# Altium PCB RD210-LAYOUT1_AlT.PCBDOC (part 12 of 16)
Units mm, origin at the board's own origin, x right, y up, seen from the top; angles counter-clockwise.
Board outline 330 x 300 mm, 6 copper layers (TOP, Mid-Layer 1, Mid-Layer 2, Mid-Layer 3, Mid-Layer 4, BOTTOM), stack 1.422 mm thick; 981 components, 463 nets, 2326 pads, 12534 vias.
Unrouted connection lines stored in the file: 6.
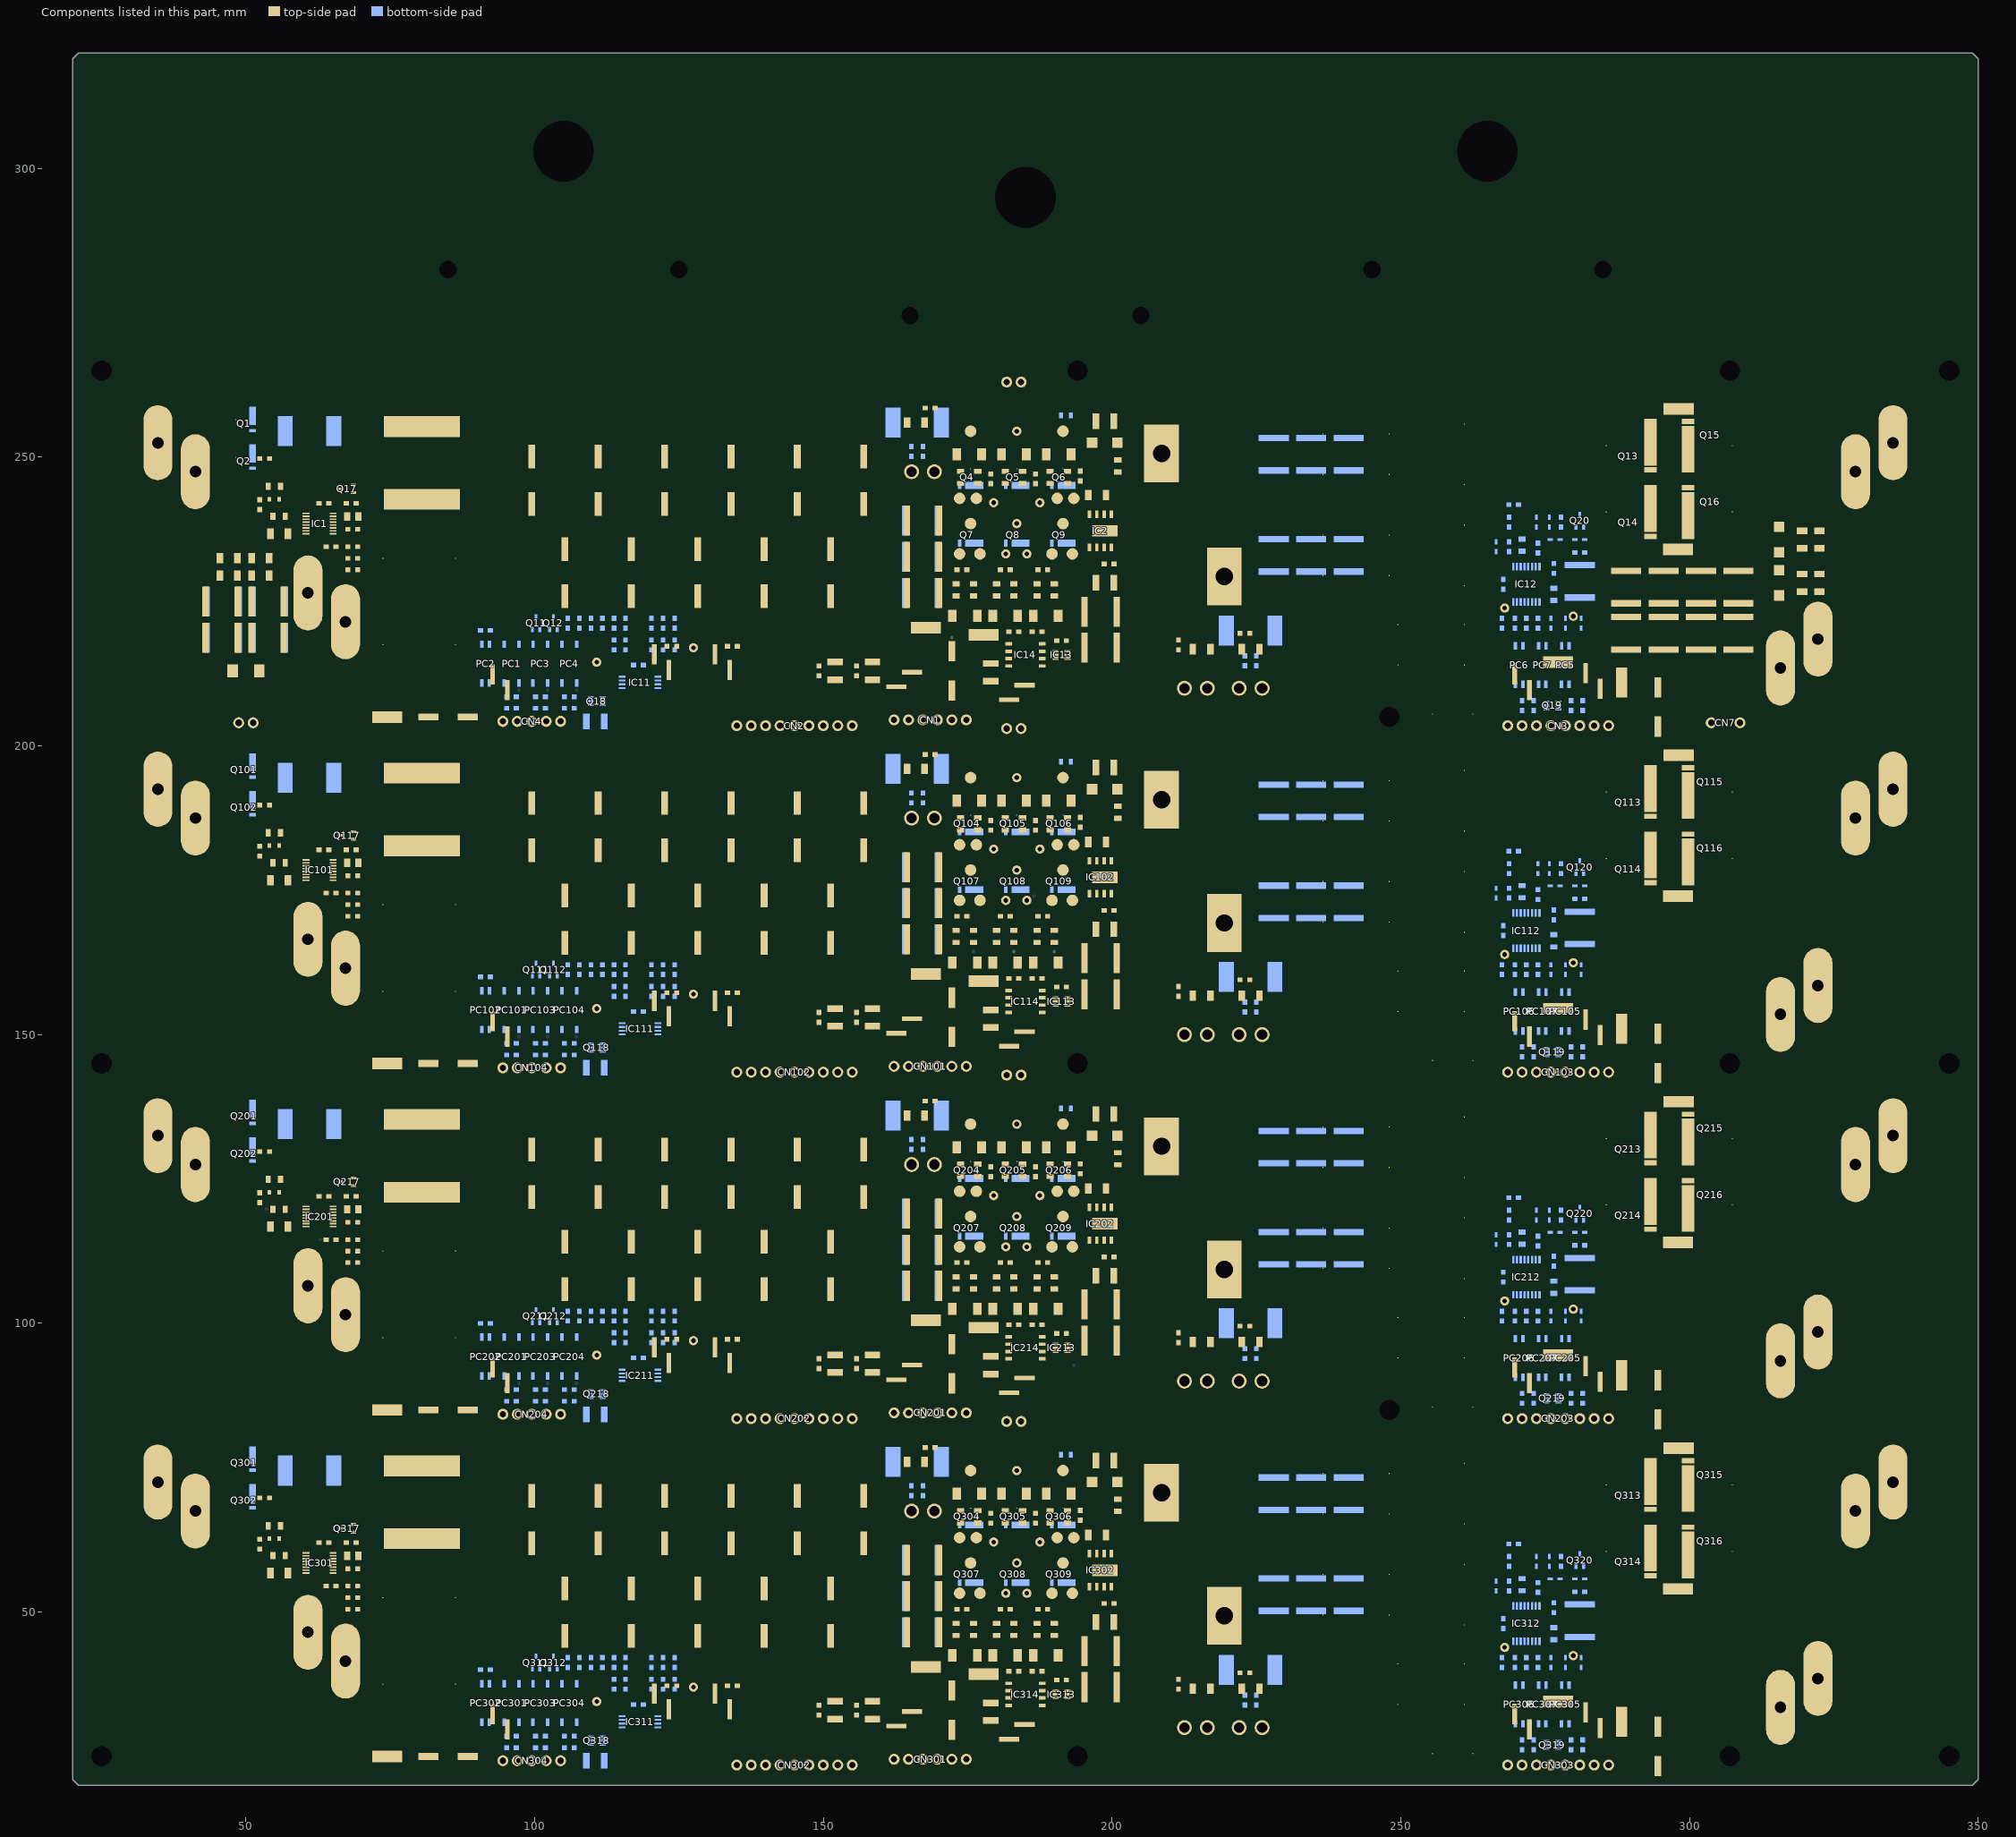
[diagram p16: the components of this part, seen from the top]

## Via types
v1: diameter 0.8, hole 0.3, TOP to BOTTOM, 12534 vias

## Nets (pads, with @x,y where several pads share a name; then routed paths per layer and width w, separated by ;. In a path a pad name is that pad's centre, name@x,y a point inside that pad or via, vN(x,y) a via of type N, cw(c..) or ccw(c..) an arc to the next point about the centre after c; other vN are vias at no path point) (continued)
pads on no net: CN2.3 CN2.4 CN2.5 CN7.2 CN102.3 CN102.4 CN102.5 CN202.3 CN202.4 CN202.5 CN302.3 CN302.4 CN302.5 IC1.3 IC1.4 IC1.7 IC1.14 IC12.11 IC12.15 IC101.3 IC101.4 IC101.7 IC101.14 IC112.11 IC112.15 IC201.3 IC201.4 IC201.7 IC201.14 IC212.11 IC212.15 IC301.3 IC301.4 IC301.7 IC301.14 IC312.11 IC312.15

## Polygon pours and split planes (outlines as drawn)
VP_L on TOP "TOP3" (solid, pour order 288): 94 vertices, not listed, extent 285,201 339,259.5
GND_P-1 on TOP "TOP4" (solid, pour order 289): 1025 vertices, not listed, extent 50.5,201 79.5,243.25
N00100041 on TOP "TOP5" (solid, pour order 290): 107 vertices, not listed, extent 61.5,29.875 89.5,79.5
VP_L on TOP "TOP10" (solid, pour order 295): 94 vertices, not listed, extent 285,21 339,79.5
VP_H on TOP "TOP11" (solid, pour order 296): 77 vertices, not listed, extent 31,141 54,199.5
VP_H on TOP "TOP12" (solid, pour order 297): 77 vertices, not listed, extent 31,81 54,139.5
VP_H on TOP "TOP13" (solid, pour order 298): 77 vertices, not listed, extent 31,21 54,79.5
GND_P-2 on TOP "TOP14" (solid, pour order 299): 985 vertices, not listed, extent 50.5,141 79.5,183.25
GND_P-3 on TOP "TOP15" (solid, pour order 300): 984 vertices, not listed, extent 50.5,81 79.5,123.25
GND_P-4 on TOP "TOP16" (solid, pour order 301): 986 vertices, not listed, extent 50.5,21 79.5,63.25
VP_L on TOP "TOP17" (solid, pour order 302): 94 vertices, not listed, extent 285,141 339,199.5
VP_L on TOP "TOP18" (solid, pour order 303): 94 vertices, not listed, extent 285,81 339,139.5
no net on TOP "TOP19" (solid, pour order 304): 41 vertices, not listed, extent 21,11 349,19
no net on TOP "TOP20" (solid, pour order 305): 41 vertices, not listed, extent 21,321 349,329
N00100195 on TOP "TOP21" (solid, pour order 306): 88 vertices, not listed, extent 199,244 213,259.5
I_SEN_N_3-1 on TOP "TOP22" (solid, pour order 307): 88 vertices, not listed, extent 214,218.5 223.5,236.125
I_SEN_N_3-2 on TOP "TOP23" (solid, pour order 308): 88 vertices, not listed, extent 214,158.5 223.5,176.125
I_SEN_N_3-3 on TOP "TOP24" (solid, pour order 309): 88 vertices, not listed, extent 214,98.5 223.5,116.125
I_SEN_N_3-4 on TOP "TOP25" (solid, pour order 310): 88 vertices, not listed, extent 214,38.5 223.5,56.125
GND-1 on TOP "TOP27" (solid, pour order 312): 44 vertices, not listed, extent 182.95,213.25 184.75,219.1
N00300246 on TOP "TOP28" (solid, pour order 313): 41 vertices, not listed, extent 171.5,253 194.75,259.5
N00300259 on TOP "TOP29" (solid, pour order 314): 280 vertices, not listed, extent 292.15,232.875 300.85,259.5
VDDIO-1 on TOP "TOP30" (solid, pour order 315): 118 vertices, not listed, extent 148.25,203.5 163.25,212.75
GND-1 on TOP "TOP31" (solid, pour order 316): 93 vertices, not listed, extent 100.5,204.879 103.5,206
GND-1 on TOP "TOP32" (solid, pour order 317): 76 vertices, not listed, extent 166,205.129 168.5,206
GND-1 on TOP "TOP33" (solid, pour order 318): 624 vertices, not listed, extent 98,201 169,216.125
VP_5R0-1 on TOP "TOP34" (solid, pour order 319): 156 vertices, not listed, extent 154.5,203.5 165.75,212.75
N00200025 on TOP "TOP35" (solid, pour order 320): 41 vertices, not listed, extent 171.5,193 194.75,199.5
N00200017 on TOP "TOP36" (solid, pour order 321): 88 vertices, not listed, extent 199,184 213,199.5
GND-2 on TOP "TOP37" (solid, pour order 322): 44 vertices, not listed, extent 182.95,153.25 184.75,159.1
N00300090 on TOP "TOP38" (solid, pour order 323): 41 vertices, not listed, extent 171.75,133 194.75,139.5
GND-2 on TOP "TOP39" (solid, pour order 324): 93 vertices, not listed, extent 100.5,144.879 103.5,146
GND-2 on TOP "TOP40" (solid, pour order 325): 76 vertices, not listed, extent 166,145.129 168.5,146
GND-2 on TOP "TOP41" (solid, pour order 326): 628 vertices, not listed, extent 98,141 169,156.125
VDDIO-2 on TOP "TOP42" (solid, pour order 327): 118 vertices, not listed, extent 148.25,143.5 163.25,152.75
VP_5R0-2 on TOP "TOP43" (solid, pour order 328): 156 vertices, not listed, extent 154.5,143.5 165.75,152.75
GND_P-1 on TOP "TOP44" (solid, pour order 329): 127 vertices, not listed, extent 285,201 327,227.75
N00300062 on TOP "TOP45" (solid, pour order 330): 88 vertices, not listed, extent 199,124 213,139.5
GND_P-2 on TOP "TOP46" (solid, pour order 331): 231 vertices, not listed, extent 285,141 327,167.75
VP_12R0_SYS_I0_0 on TOP "TOP47" (solid, pour order 332): 122 vertices, not listed, extent 182.053,209.25 201.75,232.604
GND_P-3 on TOP "TOP48" (solid, pour order 333): 65 vertices, not listed, extent 188.75,95.475 189.45,96.025
GND_P-3 on TOP "TOP49" (solid, pour order 334): 194 vertices, not listed, extent 188.75,96.76 191.725,99.375
GND_P-3 on TOP "TOP50" (solid, pour order 335): 184 vertices, not listed, extent 188.75,93.25 199.355,113.5
GND_P-3 on TOP "TOP51" (solid, pour order 336): 308 vertices, not listed, extent 185.25,93.25 193.125,106.25
GND_P-3 on TOP "TOP52" (solid, pour order 337): 445 vertices, not listed, extent 167.5,102 201,123.125
VP_12R0_SYS_I2_0 on TOP "TOP53" (solid, pour order 338): 122 vertices, not listed, extent 182.053,89.25 201.75,112.604
GND-3 on TOP "TOP54" (solid, pour order 339): 93 vertices, not listed, extent 100.5,84.879 103.5,86
GND-3 on TOP "TOP55" (solid, pour order 340): 76 vertices, not listed, extent 166,85.129 168.5,86
GND-3 on TOP "TOP56" (solid, pour order 341): 628 vertices, not listed, extent 98,81 169,96.125
VDDIO-3 on TOP "TOP57" (solid, pour order 342): 118 vertices, not listed, extent 148.25,83.5 163.25,92.75
VP_5R0-3 on TOP "TOP58" (solid, pour order 343): 156 vertices, not listed, extent 154.5,83.5 165.75,92.75
GND_P-3 on TOP "TOP59" (solid, pour order 344): 87 vertices, not listed, extent 285,81 327,107.75
GND-4 on TOP "TOP60" (solid, pour order 345): 93 vertices, not listed, extent 100.5,24.879 103.5,26
GND-4 on TOP "TOP61" (solid, pour order 346): 76 vertices, not listed, extent 166,25.129 168.5,26
GND-4 on TOP "TOP62" (solid, pour order 347): 628 vertices, not listed, extent 98,21 169,36.125
VP_5R0-4 on TOP "TOP63" (solid, pour order 348): 157 vertices, not listed, extent 154.5,23.5 165.75,32.75
VDDIO-4 on TOP "TOP64" (solid, pour order 349): 118 vertices, not listed, extent 148.25,23.5 163.25,32.75
VP_12R0_SYS_I3_0 on TOP "TOP65" (solid, pour order 350): 139 vertices, not listed, extent 182.053,29.25 201.75,52.604
GND_P-4 on TOP "TOP66" (solid, pour order 351): 65 vertices, not listed, extent 188.75,35.475 189.45,36.025
GND_P-4 on TOP "TOP67" (solid, pour order 352): 194 vertices, not listed, extent 188.75,36.76 191.725,39.375
GND_P-4 on TOP "TOP68" (solid, pour order 353): 183 vertices, not listed, extent 188.75,33.25 199.355,53.5
GND_P-4 on TOP "TOP69" (solid, pour order 354): 308 vertices, not listed, extent 185.25,33.25 193.125,46.25
GND_P-4 on TOP "TOP70" (solid, pour order 355): 447 vertices, not listed, extent 167.5,42 201,63.125
N00400068 on TOP "TOP71" (solid, pour order 356): 41 vertices, not listed, extent 171.5,73 194.75,79.5
N00400069 on TOP "TOP72" (solid, pour order 357): 88 vertices, not listed, extent 199,64 213,79.5
GND_P-4 on TOP "TOP73" (solid, pour order 358): 230 vertices, not listed, extent 285,21 327,47.75
N00100060 on TOP "TOP74" (solid, pour order 359): 280 vertices, not listed, extent 292.15,52.875 300.85,79.5
N00300065 on TOP "TOP75" (solid, pour order 360): 280 vertices, not listed, extent 292.15,112.875 300.85,139.5
N00400061 on TOP "TOP76" (solid, pour order 361): 280 vertices, not listed, extent 292.15,172.875 300.85,199.5
GND-4 on TOP "TOP77" (solid, pour order 362): 44 vertices, not listed, extent 182.95,33.25 184.75,39.1
GND-3 on TOP "TOP78" (solid, pour order 363): 44 vertices, not listed, extent 182.95,93.25 184.75,99.1
VP_12R0_SYS_I1_0 on TOP "TOP79" (solid, pour order 364): 105 vertices, not listed, extent 182.053,149.25 201.75,172.604
N00400042 on TOP "TOP82" (solid, pour order 367): 107 vertices, not listed, extent 61.5,149.875 89.5,199.5
N00300240 on TOP "TOP84" (solid, pour order 369): 107 vertices, not listed, extent 61.5,209.875 89.5,259.5
N00300046 on TOP "TOP86" (solid, pour order 371): 107 vertices, not listed, extent 61.5,89.875 89.5,139.5
N00300241 on TOP "TOP88" (solid, pour order 373): 164 vertices, not listed, extent 50.5,247.5 60.5,259.5
N00400043 on TOP "TOP89" (solid, pour order 374): 164 vertices, not listed, extent 50.5,187.5 60.5,199.5
N00300047 on TOP "TOP90" (solid, pour order 375): 164 vertices, not listed, extent 50.5,127.5 60.5,139.5
N00100042 on TOP "TOP91" (solid, pour order 376): 164 vertices, not listed, extent 50.5,67.5 60.5,79.5
GND_P-1 on TOP "TOP93" (solid, pour order 378): 41 vertices, not listed, extent 214,237.125 223.5,244
GND_P-1 on TOP "TOP94" (solid, pour order 379): 65 vertices, not listed, extent 188.75,215.475 189.45,216.025
GND_P-1 on TOP "TOP95" (solid, pour order 380): 194 vertices, not listed, extent 188.75,216.76 191.725,219.375
GND_P-1 on TOP "TOP96" (solid, pour order 381): 184 vertices, not listed, extent 188.75,213.25 199.355,233.5
GND_P-1 on TOP "TOP97" (solid, pour order 382): 308 vertices, not listed, extent 185.25,213.25 193.125,226.25
GND_P-1 on TOP "TOP98" (solid, pour order 383): 447 vertices, not listed, extent 167.5,222 201,243.125
GND_P-2 on TOP "TOP100" (solid, pour order 385): 41 vertices, not listed, extent 214,177.125 223.5,184
GND_P-3 on TOP "TOP102" (solid, pour order 387): 41 vertices, not listed, extent 214,117.125 223.5,124
GND_P-4 on TOP "TOP104" (solid, pour order 389): 41 vertices, not listed, extent 214,57.125 223.5,64
GND_P-2 on TOP "TOP105" (solid, pour order 390): 65 vertices, not listed, extent 188.75,155.475 189.45,156.025
GND_P-2 on TOP "TOP106" (solid, pour order 391): 194 vertices, not listed, extent 188.75,156.76 191.725,159.375
GND_P-2 on TOP "TOP107" (solid, pour order 392): 169 vertices, not listed, extent 188.75,153.25 199.355,173.5
GND_P-2 on TOP "TOP108" (solid, pour order 393): 308 vertices, not listed, extent 185.25,153.25 193.125,166.25
GND_P-2 on TOP "TOP109" (solid, pour order 394): 447 vertices, not listed, extent 167.5,162 201,183.125
VP_H on TOP "TOP110" (solid, pour order 395): 77 vertices, not listed, extent 31,201 54,259.5
GND_P-1 on TOP "TOP2" (solid, pour order 287): 168 vertices, not listed, extent 98,230.5 158.5,245.5
VP_H_0-1 on TOP "TOP83" (solid, pour order 368): 105 vertices, not listed, extent 72.875,216.5 167,259.5
GND_P-1 on TOP "TOP1" (solid, pour order 286): 41 vertices, not listed, extent 235,233.5 262.625,250
GND_P-1 on TOP "TOP92" (solid, pour order 377): 342 vertices, not listed, extent 202.25,201 262.5,243
VP_L_0-1 on TOP "TOP111" (solid, pour order 396): 823 vertices, not listed, extent 214,202.5 291.15,259.5
GND_P-2 on TOP "TOP6" (solid, pour order 291): 168 vertices, not listed, extent 98,170.5 158.5,185.5
VP_H_0-2 on TOP "TOP81" (solid, pour order 366): 111 vertices, not listed, extent 72.875,156.5 167,199.5
GND_P-2 on TOP "TOP80" (solid, pour order 365): 41 vertices, not listed, extent 235,173.5 262.625,190
GND_P-2 on TOP "TOP99" (solid, pour order 384): 224 vertices, not listed, extent 202.25,141 262.5,183
VP_L_0-2 on TOP "TOP112" (solid, pour order 397): 823 vertices, not listed, extent 214,142.5 291.15,199.5
GND_P-3 on TOP "TOP7" (solid, pour order 292): 168 vertices, not listed, extent 98,110.5 158.5,125.5
VP_H_0-3 on TOP "TOP85" (solid, pour order 370): 111 vertices, not listed, extent 72.875,96.5 167,139.5
GND_P-3 on TOP "TOP9" (solid, pour order 294): 41 vertices, not listed, extent 235,113.5 262.625,130
GND_P-3 on TOP "TOP101" (solid, pour order 386): 345 vertices, not listed, extent 202.25,81 262.5,123
VP_L_0-3 on TOP "TOP113" (solid, pour order 398): 821 vertices, not listed, extent 214,82.5 291.15,139.5
GND_P-4 on TOP "TOP8" (solid, pour order 293): 168 vertices, not listed, extent 98,50.5 158.5,65.5
VP_H_0-4 on TOP "TOP87" (solid, pour order 372): 111 vertices, not listed, extent 72.875,36.5 167,79.5
GND_P-4 on TOP "TOP26" (solid, pour order 311): 41 vertices, not listed, extent 235,53.5 262.625,70
GND_P-4 on TOP "TOP103" (solid, pour order 388): 224 vertices, not listed, extent 202.25,21 262.5,63
VP_L_0-4 on TOP "TOP114" (solid, pour order 399): 823 vertices, not listed, extent 214,22.5 291.15,79.5
VP_L_0-1 on Mid-Layer 1 "MID1116" (solid, pour order 217): 53 vertices, not listed, extent 214,242.125 291.15,259.5
N00300240 on Mid-Layer 1 "MID1117" (solid, pour order 218): 53 vertices, not listed, extent 61.5,244.75 89,259.5
N00300241 on Mid-Layer 1 "MID1118" (solid, pour order 219): 41 vertices, not listed, extent 50.5,245.75 60.5,259.5
N00300258 on Mid-Layer 1 "MID1119" (solid, pour order 220): 41 vertices, not listed, extent 292.15,234 300.85,259.5
N00400043 on Mid-Layer 1 "MID1120" (solid, pour order 221): 41 vertices, not listed, extent 50.5,185.75 60.5,199.5
N00400042 on Mid-Layer 1 "MID1121" (solid, pour order 222): 53 vertices, not listed, extent 61.5,184.75 89,199.5
VP_L_0-2 on Mid-Layer 1 "MID1123" (solid, pour order 224): 53 vertices, not listed, extent 214,182.125 291.15,199.5
N00300047 on Mid-Layer 1 "MID1124" (solid, pour order 225): 41 vertices, not listed, extent 50.5,125.75 60.5,139.5
N00300046 on Mid-Layer 1 "MID1125" (solid, pour order 226): 53 vertices, not listed, extent 61.5,124.75 89,139.5
VP_L_0-3 on Mid-Layer 1 "MID1127" (solid, pour order 228): 53 vertices, not listed, extent 214,122.125 291.15,139.5
N00100042 on Mid-Layer 1 "MID1128" (solid, pour order 229): 41 vertices, not listed, extent 50.5,65.75 60.5,79.5
N00100041 on Mid-Layer 1 "MID1129" (solid, pour order 230): 53 vertices, not listed, extent 61.5,64.75 89,79.5
VP_L_0-4 on Mid-Layer 1 "MID1131" (solid, pour order 232): 53 vertices, not listed, extent 214,62.125 291.15,79.5
N00400060 on Mid-Layer 1 "MID1132" (solid, pour order 233): 41 vertices, not listed, extent 292.15,174 300.85,199.5
N00300064 on Mid-Layer 1 "MID1133" (solid, pour order 234): 41 vertices, not listed, extent 292.15,114 300.85,139.5
N00100059 on Mid-Layer 1 "MID1134" (solid, pour order 235): 41 vertices, not listed, extent 292.15,54 300.85,79.5
VP_H on Mid-Layer 1 "MID1135" (solid, pour order 236): 53 vertices, not listed, extent 31,21 54,79.5
VP_H on Mid-Layer 1 "MID1136" (solid, pour order 237): 53 vertices, not listed, extent 31,81 54,139.5
VP_H on Mid-Layer 1 "MID1137" (solid, pour order 238): 53 vertices, not listed, extent 31,141 54,199.5
VP_H on Mid-Layer 1 "MID1138" (solid, pour order 239): 53 vertices, not listed, extent 31,201 54,259.5
no net on Mid-Layer 1 "MID1143" (solid, pour order 244): 41 vertices, not listed, extent 21,11 349,19
no net on Mid-Layer 1 "MID1144" (solid, pour order 245): 41 vertices, not listed, extent 21,321 349,329
VP_L on Mid-Layer 1 "MID1145" (solid, pour order 246): 169 vertices, not listed, extent 302,201 339,259.5
N00300246 on Mid-Layer 1 "MID1146" (solid, pour order 247): 41 vertices, not listed, extent 168,253 196,259.5
N00100195 on Mid-Layer 1 "MID1147" (solid, pour order 248): 77 vertices, not listed, extent 171,236.5 213,259.5
VP_H_0-1 on Mid-Layer 1 "MID1148" (solid, pour order 249): 65 vertices, not listed, extent 72.875,246.5 167,259.5
GND-1 on Mid-Layer 1 "MID1149" (solid, pour order 250): 433 vertices, not listed, extent 100.5,201 168.75,209.25
GND-1 on Mid-Layer 1 "MID1150" (solid, pour order 251): 83 vertices, not listed, extent 100.5,204.879 103.5,205.75
N00200025 on Mid-Layer 1 "MID1151" (solid, pour order 252): 41 vertices, not listed, extent 168,193 196,199.5
N00200017 on Mid-Layer 1 "MID1152" (solid, pour order 253): 77 vertices, not listed, extent 171,176.5 213,199.5
N00300090 on Mid-Layer 1 "MID1153" (solid, pour order 254): 41 vertices, not listed, extent 168,133 196,139.5
N00300062 on Mid-Layer 1 "MID1154" (solid, pour order 255): 77 vertices, not listed, extent 171,116.5 213,139.5
N00400068 on Mid-Layer 1 "MID1155" (solid, pour order 256): 41 vertices, not listed, extent 168,73 196,79.5
N00400069 on Mid-Layer 1 "MID1156" (solid, pour order 257): 77 vertices, not listed, extent 171,56.5 213,79.5
GND-2 on Mid-Layer 1 "MID1157" (solid, pour order 258): 433 vertices, not listed, extent 100.5,141 168.75,149.25
GND-2 on Mid-Layer 1 "MID1158" (solid, pour order 259): 83 vertices, not listed, extent 100.5,144.879 103.5,145.75
GND-3 on Mid-Layer 1 "MID1159" (solid, pour order 260): 433 vertices, not listed, extent 100.5,81 168.75,89.25
GND-3 on Mid-Layer 1 "MID1160" (solid, pour order 261): 83 vertices, not listed, extent 100.5,84.879 103.5,85.75
GND-4 on Mid-Layer 1 "MID1161" (solid, pour order 262): 433 vertices, not listed, extent 100.5,21 168.75,29.25
GND-4 on Mid-Layer 1 "MID1162" (solid, pour order 263): 83 vertices, not listed, extent 100.5,24.879 103.5,25.75
VP_L on Mid-Layer 1 "MID1163" (solid, pour order 264): 65 vertices, not listed, extent 302,141 339,199.5
VP_L on Mid-Layer 1 "MID1164" (solid, pour order 265): 65 vertices, not listed, extent 302,81 339,139.5
VP_L on Mid-Layer 1 "MID1165" (solid, pour order 266): 65 vertices, not listed, extent 302,21 339,79.5
VP_H_0-2 on Mid-Layer 1 "MID1166" (solid, pour order 267): 65 vertices, not listed, extent 72.875,186.5 167,199.5
VP_H_0-3 on Mid-Layer 1 "MID1167" (solid, pour order 268): 65 vertices, not listed, extent 72.875,126.5 167,139.5
VP_H_0-4 on Mid-Layer 1 "MID1168" (solid, pour order 269): 65 vertices, not listed, extent 72.875,66.5 167,79.5
N00300240 on Mid-Layer 1 "MID1115" (solid, pour order 216): 41 vertices, not listed, extent 80.5,209.875 89,236
VP_H_0-1 on Mid-Layer 1 "MID1139" (solid, pour order 240): 114 vertices, not listed, extent 103.75,223 152.75,229.5
GND_P-1 on Mid-Layer 1 "MID1181" (solid, pour order 282): 827 vertices, not listed, extent 50.5,201 201.625,245.5
I_SEN_N_3-1 on Mid-Layer 1 "MID1169" (solid, pour order 270): 41 vertices, not listed, extent 214.125,217 223.5,236.125
VP_L_0-1 on Mid-Layer 1 "MID1172" (solid, pour order 273): 104 vertices, not listed, extent 224.5,216 264.625,232.5
GND_P-1 on Mid-Layer 1 "MID1177" (solid, pour order 278): 842 vertices, not listed, extent 165.75,201 327,250
N00400042 on Mid-Layer 1 "MID1122" (solid, pour order 223): 41 vertices, not listed, extent 80.5,149.875 89,176
VP_H_0-2 on Mid-Layer 1 "MID1140" (solid, pour order 241): 114 vertices, not listed, extent 103.75,163 152.75,169.5
GND_P-2 on Mid-Layer 1 "MID1182" (solid, pour order 283): 819 vertices, not listed, extent 50.5,141 201.625,185.5
I_SEN_N_3-2 on Mid-Layer 1 "MID1171" (solid, pour order 272): 41 vertices, not listed, extent 214.125,157 223.5,176.125
VP_L_0-2 on Mid-Layer 1 "MID1173" (solid, pour order 274): 104 vertices, not listed, extent 224.5,156 264.625,172.5
GND_P-2 on Mid-Layer 1 "MID1180" (solid, pour order 281): 678 vertices, not listed, extent 165.75,141 327,190
N00300046 on Mid-Layer 1 "MID1126" (solid, pour order 227): 41 vertices, not listed, extent 80.5,89.875 89,116
VP_H_0-3 on Mid-Layer 1 "MID1141" (solid, pour order 242): 114 vertices, not listed, extent 103.75,103 152.75,109.5
GND_P-3 on Mid-Layer 1 "MID1183" (solid, pour order 284): 823 vertices, not listed, extent 50.5,81 201.625,125.5
I_SEN_N_3-3 on Mid-Layer 1 "MID1170" (solid, pour order 271): 41 vertices, not listed, extent 214.125,97 223.5,116.125
VP_L_0-3 on Mid-Layer 1 "MID1174" (solid, pour order 275): 104 vertices, not listed, extent 224.5,96 264.625,112.5
GND_P-3 on Mid-Layer 1 "MID1179" (solid, pour order 280): 692 vertices, not listed, extent 165.75,81 327,130
N00100041 on Mid-Layer 1 "MID1130" (solid, pour order 231): 41 vertices, not listed, extent 80.5,29.875 89,56
VP_H_0-4 on Mid-Layer 1 "MID1142" (solid, pour order 243): 114 vertices, not listed, extent 103.75,43 152.75,49.5
GND_P-4 on Mid-Layer 1 "MID1184" (solid, pour order 285): 822 vertices, not listed, extent 50.5,21 201.625,65.5
VP_L_0-4 on Mid-Layer 1 "MID1175" (solid, pour order 276): 104 vertices, not listed, extent 224.5,36 264.625,52.5
I_SEN_N_3-4 on Mid-Layer 1 "MID1176" (solid, pour order 277): 41 vertices, not listed, extent 214.125,37 223.5,56.05
GND_P-4 on Mid-Layer 1 "MID1178" (solid, pour order 279): 677 vertices, not listed, extent 165.75,21 327,70
VP_H_0-1 on Mid-Layer 2 "MID2186" (solid, pour order 154): 65 vertices, not listed, extent 72.875,246.5 167,259.5
VP_L_0-1 on Mid-Layer 2 "MID2187" (solid, pour order 155): 53 vertices, not listed, extent 214,242.125 291.15,259.5
N00300258 on Mid-Layer 2 "MID2188" (solid, pour order 156): 41 vertices, not listed, extent 292.15,234 300.85,259.5
N00300240 on Mid-Layer 2 "MID2189" (solid, pour order 157): 53 vertices, not listed, extent 61.5,244.75 89,259.5
N00300241 on Mid-Layer 2 "MID2190" (solid, pour order 158): 41 vertices, not listed, extent 50.5,245.75 60.5,259.5
N00400043 on Mid-Layer 2 "MID2191" (solid, pour order 159): 41 vertices, not listed, extent 50.5,185.75 60.5,199.5
N00400042 on Mid-Layer 2 "MID2192" (solid, pour order 160): 53 vertices, not listed, extent 61.5,184.75 89,199.5
VP_L_0-2 on Mid-Layer 2 "MID2193" (solid, pour order 161): 53 vertices, not listed, extent 214,182.125 291.15,199.5
N00300047 on Mid-Layer 2 "MID2194" (solid, pour order 162): 41 vertices, not listed, extent 50.5,125.75 60.5,139.5
N00300046 on Mid-Layer 2 "MID2195" (solid, pour order 163): 53 vertices, not listed, extent 61.5,124.75 89,139.5
VP_L_0-3 on Mid-Layer 2 "MID2197" (solid, pour order 165): 53 vertices, not listed, extent 214,122.125 291.15,139.5
N00100042 on Mid-Layer 2 "MID2198" (solid, pour order 166): 41 vertices, not listed, extent 50.5,65.75 60.5,79.5
N00100041 on Mid-Layer 2 "MID2199" (solid, pour order 167): 53 vertices, not listed, extent 61.5,64.75 89,79.5
VP_L_0-4 on Mid-Layer 2 "MID2201" (solid, pour order 169): 53 vertices, not listed, extent 214,62.125 291.15,79.5
N00400060 on Mid-Layer 2 "MID2202" (solid, pour order 170): 41 vertices, not listed, extent 292.15,174 300.85,199.5
N00300064 on Mid-Layer 2 "MID2203" (solid, pour order 171): 41 vertices, not listed, extent 292.15,114 300.85,139.5
N00100059 on Mid-Layer 2 "MID2204" (solid, pour order 172): 41 vertices, not listed, extent 292.15,54 300.85,79.5
VP_H on Mid-Layer 2 "MID2205" (solid, pour order 173): 53 vertices, not listed, extent 31,141 54,199.5
VP_H on Mid-Layer 2 "MID2206" (solid, pour order 174): 53 vertices, not listed, extent 31,201 54,259.5
VP_H on Mid-Layer 2 "MID2207" (solid, pour order 175): 53 vertices, not listed, extent 31,81 54,139.5
VP_H on Mid-Layer 2 "MID2208" (solid, pour order 176): 53 vertices, not listed, extent 31,21 54,79.5
VP_L on Mid-Layer 2 "MID2209" (solid, pour order 177): 65 vertices, not listed, extent 302,141 339,199.5
no net on Mid-Layer 2 "MID2214" (solid, pour order 182): 41 vertices, not listed, extent 21,11 349,19
no net on Mid-Layer 2 "MID2215" (solid, pour order 183): 41 vertices, not listed, extent 21,321 349,329
VP_L on Mid-Layer 2 "MID2216" (solid, pour order 184): 169 vertices, not listed, extent 302,201 339,259.5
N00100195 on Mid-Layer 2 "MID2217" (solid, pour order 185): 53 vertices, not listed, extent 171,244 213,259.5
N00300246 on Mid-Layer 2 "MID2218" (solid, pour order 186): 41 vertices, not listed, extent 168,253 196,259.5
N00200025 on Mid-Layer 2 "MID2219" (solid, pour order 187): 41 vertices, not listed, extent 168,193 196,199.5
N00300090 on Mid-Layer 2 "MID2220" (solid, pour order 188): 41 vertices, not listed, extent 168,133 196,139.5
N00400068 on Mid-Layer 2 "MID2221" (solid, pour order 189): 41 vertices, not listed, extent 168,73 196,79.5
N00200017 on Mid-Layer 2 "MID2222" (solid, pour order 190): 53 vertices, not listed, extent 171,184 213,199.5
N00300062 on Mid-Layer 2 "MID2223" (solid, pour order 191): 53 vertices, not listed, extent 171,124 213,139.5
N00400069 on Mid-Layer 2 "MID2224" (solid, pour order 192): 53 vertices, not listed, extent 171,64 213,79.5
VP_H_0-2 on Mid-Layer 2 "MID2225" (solid, pour order 193): 65 vertices, not listed, extent 72.875,186.5 167,199.5
VP_L on Mid-Layer 2 "MID2226" (solid, pour order 194): 65 vertices, not listed, extent 302,81 339,139.5
VP_L on Mid-Layer 2 "MID2227" (solid, pour order 195): 65 vertices, not listed, extent 302,21 339,79.5
VP_H_0-3 on Mid-Layer 2 "MID2228" (solid, pour order 196): 65 vertices, not listed, extent 72.875,126.5 167,139.5
VP_H_0-3 on Mid-Layer 2 "MID2229" (solid, pour order 197): 65 vertices, not listed, extent 72.875,126.5 167,139.5
VP_H_0-4 on Mid-Layer 2 "MID2230" (solid, pour order 198): 65 vertices, not listed, extent 72.875,66.5 167,79.5
GND_P-1 on Mid-Layer 2 "MID2233" (solid, pour order 201): 273 vertices, not listed, extent 92,201 169.5,220
GND_P-2 on Mid-Layer 2 "MID2237" (solid, pour order 205): 273 vertices, not listed, extent 92,141 169.5,160
GND_P-3 on Mid-Layer 2 "MID2238" (solid, pour order 206): 273 vertices, not listed, extent 92,81 169.5,100
GND_P-4 on Mid-Layer 2 "MID2239" (solid, pour order 207): 273 vertices, not listed, extent 92,21 169.5,40
N00300240 on Mid-Layer 2 "MID2185" (solid, pour order 153): 41 vertices, not listed, extent 80.5,209.875 89,236
VP_H_0-1 on Mid-Layer 2 "MID2231" (solid, pour order 199): 114 vertices, not listed, extent 103.75,223 152.75,229.5
VP_L_0-1 on Mid-Layer 2 "MID2232" (solid, pour order 200): 104 vertices, not listed, extent 224.5,216 264.625,232.5
I_SEN_N_3-1 on Mid-Layer 2 "MID2240" (solid, pour order 208): 41 vertices, not listed, extent 214.125,217 223.5,236.125
GND_P-1 on Mid-Layer 2 "MID2244" (solid, pour order 212): 1141 vertices, not listed, extent 50.5,201 327,250
N00400042 on Mid-Layer 2 "MID2210" (solid, pour order 178): 41 vertices, not listed, extent 80.5,149.875 89,176
VP_H_0-2 on Mid-Layer 2 "MID2211" (solid, pour order 179): 114 vertices, not listed, extent 103.75,163 152.75,169.5
VP_L_0-2 on Mid-Layer 2 "MID2234" (solid, pour order 202): 104 vertices, not listed, extent 224.5,156 264.625,172.5
I_SEN_N_3-2 on Mid-Layer 2 "MID2241" (solid, pour order 209): 41 vertices, not listed, extent 214.125,157 223.5,176.05
GND_P-2 on Mid-Layer 2 "MID2245" (solid, pour order 213): 1096 vertices, not listed, extent 50.5,141 327,190
N00300046 on Mid-Layer 2 "MID2196" (solid, pour order 164): 41 vertices, not listed, extent 80.5,89.875 89,116
VP_H_0-3 on Mid-Layer 2 "MID2212" (solid, pour order 180): 114 vertices, not listed, extent 103.75,103 152.75,109.5
VP_L_0-3 on Mid-Layer 2 "MID2235" (solid, pour order 203): 104 vertices, not listed, extent 224.5,96 264.625,112.5
I_SEN_N_3-3 on Mid-Layer 2 "MID2242" (solid, pour order 210): 41 vertices, not listed, extent 214.125,97 223.5,116.05
GND_P-3 on Mid-Layer 2 "MID2246" (solid, pour order 214): 1077 vertices, not listed, extent 50.5,80.98 327,130
N00100041 on Mid-Layer 2 "MID2200" (solid, pour order 168): 41 vertices, not listed, extent 80.5,29.875 89,56
VP_H_0-4 on Mid-Layer 2 "MID2213" (solid, pour order 181): 114 vertices, not listed, extent 103.75,43 152.75,49.5
VP_L_0-4 on Mid-Layer 2 "MID2236" (solid, pour order 204): 104 vertices, not listed, extent 224.5,36 264.625,52.5
I_SEN_N_3-4 on Mid-Layer 2 "MID2243" (solid, pour order 211): 41 vertices, not listed, extent 214.125,37 223.5,56.05
GND_P-4 on Mid-Layer 2 "MID2247" (solid, pour order 215): 1097 vertices, not listed, extent 50.5,21 327,70
VP_H_0-1 on Mid-Layer 3 "MID3248" (solid, pour order 91): 65 vertices, not listed, extent 72.875,246.5 167,259.5
N00300241 on Mid-Layer 3 "MID3250" (solid, pour order 93): 41 vertices, not listed, extent 50.5,245.75 60.5,259.5
N00300258 on Mid-Layer 3 "MID3251" (solid, pour order 94): 41 vertices, not listed, extent 292.15,234 300.85,259.5
VP_L_0-1 on Mid-Layer 3 "MID3252" (solid, pour order 95): 53 vertices, not listed, extent 214,242.125 291.15,259.5
N00300240 on Mid-Layer 3 "MID3253" (solid, pour order 96): 53 vertices, not listed, extent 61.5,244.75 89,259.5
N00300246 on Mid-Layer 3 "MID3254" (solid, pour order 97): 41 vertices, not listed, extent 168,253 196,259.5
VP_H on Mid-Layer 3 "MID3255" (solid, pour order 98): 53 vertices, not listed, extent 31,21 54,79.5
N00400043 on Mid-Layer 3 "MID3256" (solid, pour order 99): 41 vertices, not listed, extent 50.5,185.75 60.5,199.5
N00400042 on Mid-Layer 3 "MID3257" (solid, pour order 100): 53 vertices, not listed, extent 61.5,184.75 89,199.5
VP_L_0-2 on Mid-Layer 3 "MID3259" (solid, pour order 102): 53 vertices, not listed, extent 214,182.125 291.15,199.5
N00400060 on Mid-Layer 3 "MID3260" (solid, pour order 103): 41 vertices, not listed, extent 292.15,174 300.85,199.5
N00300064 on Mid-Layer 3 "MID3261" (solid, pour order 104): 41 vertices, not listed, extent 292.15,114 300.85,139.5
N00100059 on Mid-Layer 3 "MID3262" (solid, pour order 105): 41 vertices, not listed, extent 292.15,54 300.85,79.5
VP_L_0-3 on Mid-Layer 3 "MID3263" (solid, pour order 106): 53 vertices, not listed, extent 214,122.125 291.15,139.5
N00300046 on Mid-Layer 3 "MID3265" (solid, pour order 108): 53 vertices, not listed, extent 61.5,124.75 89,139.5
N00300047 on Mid-Layer 3 "MID3266" (solid, pour order 109): 41 vertices, not listed, extent 50.5,125.75 60.5,139.5
N00100042 on Mid-Layer 3 "MID3267" (solid, pour order 110): 41 vertices, not listed, extent 50.5,65.75 60.5,79.5
N00100041 on Mid-Layer 3 "MID3268" (solid, pour order 111): 53 vertices, not listed, extent 61.5,64.75 89,79.5
VP_L_0-4 on Mid-Layer 3 "MID3270" (solid, pour order 113): 53 vertices, not listed, extent 214,62.125 291.15,79.5
VP_H on Mid-Layer 3 "MID3271" (solid, pour order 114): 53 vertices, not listed, extent 31,81 54,139.5
VP_H on Mid-Layer 3 "MID3272" (solid, pour order 115): 53 vertices, not listed, extent 31,141 54,199.5
VP_H on Mid-Layer 3 "MID3273" (solid, pour order 116): 53 vertices, not listed, extent 31,201 54,259.5
no net on Mid-Layer 3 "MID3278" (solid, pour order 121): 41 vertices, not listed, extent 21,11 349,19
no net on Mid-Layer 3 "MID3279" (solid, pour order 122): 41 vertices, not listed, extent 21,321 349,329
VP_L on Mid-Layer 3 "MID3280" (solid, pour order 123): 169 vertices, not listed, extent 302,201 339,259.5
N00100195 on Mid-Layer 3 "MID3281" (solid, pour order 124): 53 vertices, not listed, extent 171,244 213,259.5
VP_L on Mid-Layer 3 "MID3282" (solid, pour order 125): 65 vertices, not listed, extent 302,141 339,199.5
N00200025 on Mid-Layer 3 "MID3283" (solid, pour order 126): 41 vertices, not listed, extent 168,193 196,199.5
N00200017 on Mid-Layer 3 "MID3284" (solid, pour order 127): 53 vertices, not listed, extent 171,184 213,199.5
N00300090 on Mid-Layer 3 "MID3285" (solid, pour order 128): 41 vertices, not listed, extent 168,133 196,139.5
N00300062 on Mid-Layer 3 "MID3286" (solid, pour order 129): 53 vertices, not listed, extent 171,124 213,139.5
N00400068 on Mid-Layer 3 "MID3287" (solid, pour order 130): 41 vertices, not listed, extent 168,73 196,79.5
N00400069 on Mid-Layer 3 "MID3288" (solid, pour order 131): 53 vertices, not listed, extent 171,64 213,79.5
VP_H_0-3 on Mid-Layer 3 "MID3289" (solid, pour order 132): 109 vertices, not listed, extent 72.925,126.55 166.95,139.45
VP_L on Mid-Layer 3 "MID3290" (solid, pour order 133): 65 vertices, not listed, extent 302,81 339,139.5
VP_L on Mid-Layer 3 "MID3291" (solid, pour order 134): 65 vertices, not listed, extent 302,21 339,79.5
VP_H_0-4 on Mid-Layer 3 "MID3292" (solid, pour order 135): 109 vertices, not listed, extent 72.925,66.55 166.95,79.45
VP_H_0-2 on Mid-Layer 3 "MID3293" (solid, pour order 136): 109 vertices, not listed, extent 72.925,186.55 166.95,199.45
GND_P-1 on Mid-Layer 3 "MID3299" (solid, pour order 142): 1267 vertices, not listed, extent 92,201 169.5,220
GND_P-2 on Mid-Layer 3 "MID3300" (solid, pour order 143): 1279 vertices, not listed, extent 92,141 169.5,160
GND_P-3 on Mid-Layer 3 "MID3301" (solid, pour order 144): 1284 vertices, not listed, extent 92,81 169.5,100
GND_P-4 on Mid-Layer 3 "MID3302" (solid, pour order 145): 1281 vertices, not listed, extent 92,21 169.5,40
N00300240 on Mid-Layer 3 "MID3249" (solid, pour order 92): 41 vertices, not listed, extent 80.5,209.875 89,236
VP_H_0-1 on Mid-Layer 3 "MID3274" (solid, pour order 117): 114 vertices, not listed, extent 103.75,223 152.75,229.5
I_SEN_N_3-1 on Mid-Layer 3 "MID3294" (solid, pour order 137): 41 vertices, not listed, extent 214.125,217 223.5,236.125
VP_L_0-1 on Mid-Layer 3 "MID3295" (solid, pour order 138): 104 vertices, not listed, extent 224.5,216 264.625,232.5
GND_P-1 on Mid-Layer 3 "MID3306" (solid, pour order 149): 1142 vertices, not listed, extent 50.5,201 327,250
N00400042 on Mid-Layer 3 "MID3258" (solid, pour order 101): 41 vertices, not listed, extent 80.5,149.875 89,176
VP_H_0-2 on Mid-Layer 3 "MID3275" (solid, pour order 118): 114 vertices, not listed, extent 103.75,163 152.75,169.5
VP_L_0-2 on Mid-Layer 3 "MID3296" (solid, pour order 139): 104 vertices, not listed, extent 224.5,156 264.625,172.5
I_SEN_N_3-2 on Mid-Layer 3 "MID3305" (solid, pour order 148): 41 vertices, not listed, extent 214.125,157 223.5,176.05
GND_P-2 on Mid-Layer 3 "MID3307" (solid, pour order 150): 1097 vertices, not listed, extent 50.5,141 327,190
N00300046 on Mid-Layer 3 "MID3264" (solid, pour order 107): 41 vertices, not listed, extent 80.5,89.875 89,116
VP_H_0-3 on Mid-Layer 3 "MID3276" (solid, pour order 119): 114 vertices, not listed, extent 103.75,103 152.75,109.5
VP_L_0-3 on Mid-Layer 3 "MID3297" (solid, pour order 140): 104 vertices, not listed, extent 224.5,96 264.625,112.5
I_SEN_N_3-3 on Mid-Layer 3 "MID3304" (solid, pour order 147): 41 vertices, not listed, extent 214.125,97 223.5,116.05
GND_P-3 on Mid-Layer 3 "MID3308" (solid, pour order 151): 1047 vertices, not listed, extent 50.5,81 327,130
N00100041 on Mid-Layer 3 "MID3269" (solid, pour order 112): 41 vertices, not listed, extent 80.5,29.875 89,56
VP_H_0-4 on Mid-Layer 3 "MID3277" (solid, pour order 120): 114 vertices, not listed, extent 103.75,43 152.75,49.5
VP_L_0-4 on Mid-Layer 3 "MID3298" (solid, pour order 141): 104 vertices, not listed, extent 224.5,36 264.625,52.5
I_SEN_N_3-4 on Mid-Layer 3 "MID3303" (solid, pour order 146): 41 vertices, not listed, extent 214.125,37 223.5,56.05
GND_P-4 on Mid-Layer 3 "MID3309" (solid, pour order 152): 1098 vertices, not listed, extent 50.5,21 327,70
no net on Mid-Layer 4 "MID4310" (solid, pour order 84): 41 vertices, not listed, extent 21,11 349,19
no net on Mid-Layer 4 "MID4311" (solid, pour order 85): 41 vertices, not listed, extent 21,321 349,329
GND_P-1 on Mid-Layer 4 "MID4312" (solid, pour order 86): 11276 vertices, not listed, extent 44.625,201 288,260
GND_P-2 on Mid-Layer 4 "MID4313" (solid, pour order 87): 11477 vertices, not listed, extent 44.625,141 288,200
GND_P-3 on Mid-Layer 4 "MID4314" (solid, pour order 88): 11466 vertices, not listed, extent 44.625,81 288,140
GND_P-3 on Mid-Layer 4 "MID4315" (solid, pour order 89): 224.911,131.219 ccw(c224.986,131.219) 225.061,131.219 ccw(c224.986,131.219)
GND_P-4 on Mid-Layer 4 "MID4316" (solid, pour order 90): 11452 vertices, not listed, extent 44.625,21 288,80
VP_H_0-1 on BOTTOM "BOTTOM317" (solid, pour order 2): 41 vertices, not listed, extent 72.875,249.5 88.75,259.5
VP_L_0-1 on BOTTOM "BOTTOM318" (solid, pour order 3): 41 vertices, not listed, extent 214,251 244.5,259.5
VP_L on BOTTOM "BOTTOM319" (solid, pour order 4): 41 vertices, not listed, extent 325.5,240.5 338.5,259.5
GND_P-1 on BOTTOM "BOTTOM320" (solid, pour order 5): 41 vertices, not listed, extent 313,206.5 325,225.5
N00300240 on BOTTOM "BOTTOM321" (solid, pour order 6): 77 vertices, not listed, extent 61.5,240.625 89,259.5
VP_H on BOTTOM "BOTTOM322" (solid, pour order 7): 53 vertices, not listed, extent 31,239.25 49.75,259.5
GND_P-1 on BOTTOM "BOTTOM323" (solid, pour order 8): 59 vertices, not listed, extent 54.5,214.5 70,233.125
VP_H on BOTTOM "BOTTOM324" (solid, pour order 9): 41 vertices, not listed, extent 31,215.5 45.5,228.5
VP_H on BOTTOM "BOTTOM325" (solid, pour order 10): 41 vertices, not listed, extent 31,155.5 45.5,168.5
VP_H on BOTTOM "BOTTOM326" (solid, pour order 11): 53 vertices, not listed, extent 31,179.25 49.75,199.5
VP_H on BOTTOM "BOTTOM327" (solid, pour order 12): 41 vertices, not listed, extent 31,95.5 45.5,108.5
VP_H on BOTTOM "BOTTOM328" (solid, pour order 13): 53 vertices, not listed, extent 31,119.25 49.75,139.5
VP_H on BOTTOM "BOTTOM329" (solid, pour order 14): 41 vertices, not listed, extent 31,35.5 45.5,48.5
VP_H on BOTTOM "BOTTOM330" (solid, pour order 15): 53 vertices, not listed, extent 31,59.25 49.75,79.5
VP_L_0-2 on BOTTOM "BOTTOM331" (solid, pour order 16): 41 vertices, not listed, extent 214,191 244.5,199.5
VP_L_0-3 on BOTTOM "BOTTOM332" (solid, pour order 17): 41 vertices, not listed, extent 214,131 244.5,139.5
VP_L_0-4 on BOTTOM "BOTTOM333" (solid, pour order 18): 41 vertices, not listed, extent 214,71 244.5,79.5
GND_P-2 on BOTTOM "BOTTOM334" (solid, pour order 19): 41 vertices, not listed, extent 313,146.5 325,165.5
GND_P-3 on BOTTOM "BOTTOM335" (solid, pour order 20): 41 vertices, not listed, extent 313,86.5 325,105.5
GND_P-4 on BOTTOM "BOTTOM336" (solid, pour order 21): 41 vertices, not listed, extent 313,26.5 325,45.5
VP_L on BOTTOM "BOTTOM337" (solid, pour order 22): 41 vertices, not listed, extent 325.5,180.5 338.5,199.5
VP_L on BOTTOM "BOTTOM338" (solid, pour order 23): 41 vertices, not listed, extent 325.5,120.5 338.5,139.5
VP_L on BOTTOM "BOTTOM339" (solid, pour order 24): 41 vertices, not listed, extent 325.5,60.5 338.5,79.5
GND_P-2 on BOTTOM "BOTTOM340" (solid, pour order 25): 59 vertices, not listed, extent 54.5,154.5 70,173.125
GND_P-3 on BOTTOM "BOTTOM341" (solid, pour order 26): 59 vertices, not listed, extent 54.5,94.5 70,113.125
GND_P-4 on BOTTOM "BOTTOM342" (solid, pour order 27): 59 vertices, not listed, extent 54.5,34.5 70,53.125
N00400042 on BOTTOM "BOTTOM343" (solid, pour order 28): 77 vertices, not listed, extent 61.5,180.625 89,199.5
N00300046 on BOTTOM "BOTTOM344" (solid, pour order 29): 77 vertices, not listed, extent 61.5,120.625 89,139.5
N00100041 on BOTTOM "BOTTOM345" (solid, pour order 30): 77 vertices, not listed, extent 61.5,60.625 89,79.5
VP_H_0-4 on BOTTOM "BOTTOM346" (solid, pour order 31): 41 vertices, not listed, extent 72.875,69.5 88.75,79.5
VP_H_0-2 on BOTTOM "BOTTOM347" (solid, pour order 32): 41 vertices, not listed, extent 72.875,189.5 88.75,199.5
VP_H_0-3 on BOTTOM "BOTTOM348" (solid, pour order 33): 41 vertices, not listed, extent 72.875,129.5 88.75,139.5
no net on BOTTOM "BOTTOM349" (solid, pour order 34): 41 vertices, not listed, extent 21,11 349,19
no net on BOTTOM "BOTTOM350" (solid, pour order 35): 41 vertices, not listed, extent 21,321 349,329
I_SEN_N_3-1 on BOTTOM "BOTTOM351" (solid, pour order 36): 53 vertices, not listed, extent 214,217 223.5,236.125
I_SEN_N_3-2 on BOTTOM "BOTTOM352" (solid, pour order 37): 53 vertices, not listed, extent 214,157 223.5,176.125
I_SEN_N_3-4 on BOTTOM "BOTTOM353" (solid, pour order 38): 53 vertices, not listed, extent 214,37 223.5,56.125
I_SEN_N_3-3 on BOTTOM "BOTTOM354" (solid, pour order 39): 53 vertices, not listed, extent 214,97 223.5,116.125
N00100195 on BOTTOM "BOTTOM355" (solid, pour order 40): 241 vertices, not listed, extent 172.25,236.7 213,259.5
GND-1 on BOTTOM "BOTTOM356" (solid, pour order 41): 482 vertices, not listed, extent 274.5,204.129 283.136,211.869
GND-1 on BOTTOM "BOTTOM357" (solid, pour order 42): 3339 vertices, not listed, extent 91.5,201 282.5,219
GND_P-1 on BOTTOM "BOTTOM358" (solid, pour order 43): 365 vertices, not listed, extent 167.5,223 244.5,250
GND_P-2 on BOTTOM "BOTTOM359" (solid, pour order 44): 364 vertices, not listed, extent 167.5,163 244.5,190
N00200017 on BOTTOM "BOTTOM360" (solid, pour order 45): 239 vertices, not listed, extent 172.25,176.7 213,199.5
GND-2 on BOTTOM "BOTTOM361" (solid, pour order 46): 482 vertices, not listed, extent 274.5,144.129 283.136,151.869
GND-2 on BOTTOM "BOTTOM362" (solid, pour order 47): 3332 vertices, not listed, extent 91.5,141 282.5,159
GND_P-3 on BOTTOM "BOTTOM363" (solid, pour order 48): 363 vertices, not listed, extent 167.5,103 244.5,130
N00300062 on BOTTOM "BOTTOM364" (solid, pour order 49): 239 vertices, not listed, extent 172.25,116.7 213,139.5
GND-3 on BOTTOM "BOTTOM365" (solid, pour order 50): 485 vertices, not listed, extent 274.5,84.129 283.136,91.869
GND-3 on BOTTOM "BOTTOM366" (solid, pour order 51): 3332 vertices, not listed, extent 91.5,81 282.5,99
GND_P-4 on BOTTOM "BOTTOM367" (solid, pour order 52): 364 vertices, not listed, extent 167.5,43 244.5,70
N00400069 on BOTTOM "BOTTOM368" (solid, pour order 53): 241 vertices, not listed, extent 172.25,56.7 213,79.5
GND-4 on BOTTOM "BOTTOM369" (solid, pour order 54): 485 vertices, not listed, extent 274.5,24.129 283.136,31.869
GND-4 on BOTTOM "BOTTOM370" (solid, pour order 55): 3333 vertices, not listed, extent 91.5,21 282.5,39
VP_H_0-4 on BOTTOM "BOTTOM371" (solid, pour order 56): 77 vertices, not listed, extent 134.625,43 166.5,79
N00300090 on BOTTOM "BOTTOM372" (solid, pour order 57): 77 vertices, not listed, extent 169.125,126.7 196,139
VP_H_0-3 on BOTTOM "BOTTOM373" (solid, pour order 58): 77 vertices, not listed, extent 134.625,103 166.5,139
N00400068 on BOTTOM "BOTTOM374" (solid, pour order 59): 77 vertices, not listed, extent 169.125,66.7 196,79
VP_H_0-2 on BOTTOM "BOTTOM375" (solid, pour order 60): 77 vertices, not listed, extent 134.625,163 166.5,199
N00200025 on BOTTOM "BOTTOM376" (solid, pour order 61): 77 vertices, not listed, extent 169.125,186.7 196,199
VP_H_0-1 on BOTTOM "BOTTOM377" (solid, pour order 62): 77 vertices, not listed, extent 134.625,223 166.5,259
N00300246 on BOTTOM "BOTTOM378" (solid, pour order 63): 77 vertices, not listed, extent 169.125,246.7 196,259
GND_P-1 on BOTTOM "BOTTOM379" (solid, pour order 64): 44 vertices, not listed, extent 268.978,223.375 270.4,224.05
GND_P-1 on BOTTOM "BOTTOM380" (solid, pour order 65): 106 vertices, not listed, extent 273,221.125 275.638,223.466
GND_P-1 on BOTTOM "BOTTOM381" (solid, pour order 66): 1155 vertices, not listed, extent 265.5,221.125 284.375,234.494
GND_P-3 on BOTTOM "BOTTOM382" (solid, pour order 67): 44 vertices, not listed, extent 268.978,103.375 270.4,104.05
GND_P-3 on BOTTOM "BOTTOM383" (solid, pour order 68): 106 vertices, not listed, extent 273,101.125 275.638,103.466
GND_P-3 on BOTTOM "BOTTOM384" (solid, pour order 69): 1155 vertices, not listed, extent 265.5,101.125 284.375,114.494
GND_P-2 on BOTTOM "BOTTOM385" (solid, pour order 70): 44 vertices, not listed, extent 268.978,163.375 270.4,164.05
GND_P-2 on BOTTOM "BOTTOM386" (solid, pour order 71): 94 vertices, not listed, extent 273,161.125 275.625,163.453
GND_P-2 on BOTTOM "BOTTOM387" (solid, pour order 72): 1155 vertices, not listed, extent 265.5,161.125 284.375,174.494
GND_P-4 on BOTTOM "BOTTOM388" (solid, pour order 73): 44 vertices, not listed, extent 268.978,43.375 270.4,44.05
GND_P-4 on BOTTOM "BOTTOM389" (solid, pour order 74): 106 vertices, not listed, extent 273,41.125 275.638,43.466
GND_P-4 on BOTTOM "BOTTOM390" (solid, pour order 75): 1155 vertices, not listed, extent 265.5,41.125 284.375,54.494
N00300241 on BOTTOM "BOTTOM391" (solid, pour order 76): 148 vertices, not listed, extent 50.55,247.25 60.5,259.5
N00400043 on BOTTOM "BOTTOM392" (solid, pour order 77): 148 vertices, not listed, extent 50.55,187.25 60.5,199.5
N00300047 on BOTTOM "BOTTOM393" (solid, pour order 78): 148 vertices, not listed, extent 50.55,127.25 60.5,139.5
N00100042 on BOTTOM "BOTTOM394" (solid, pour order 79): 148 vertices, not listed, extent 50.55,67.25 60.5,79.5
VP_L_0-1 on BOTTOM "BOTTOM395" (solid, pour order 80): 107 vertices, not listed, extent 224.5,215.75 264.5,232.5
VP_L_0-2 on BOTTOM "BOTTOM396" (solid, pour order 81): 107 vertices, not listed, extent 224.5,155.75 264.5,172.5
VP_L_0-3 on BOTTOM "BOTTOM397" (solid, pour order 82): 107 vertices, not listed, extent 224.5,95.75 264.5,112.5
VP_L_0-4 on BOTTOM "BOTTOM398" (solid, pour order 83): 107 vertices, not listed, extent 224.5,35.75 264.5,52.5
no net on Top Overlay "TOPOVERLAY399" (solid, pour order 0): 100.325,242.15 102.69,242.15 cw(c99.5,246) 100.325,241.069
no net on Top Overlay "TOPOVERLAY400" (solid, pour order 0): 98.675,241.069 cw(c99.5,246) 96.31,242.15 98.675,242.15
no net on Top Overlay "TOPOVERLAY401" (solid, pour order 0): 111.825,242.15 114.19,242.15 cw(c111,246) 111.825,241.069
no net on Top Overlay "TOPOVERLAY402" (solid, pour order 0): 110.175,241.069 cw(c111,246) 107.81,242.15 110.175,242.15
no net on Top Overlay "TOPOVERLAY403" (solid, pour order 0): 123.325,242.15 125.69,242.15 cw(c122.5,246) 123.325,241.069
no net on Top Overlay "TOPOVERLAY404" (solid, pour order 0): 121.675,241.069 cw(c122.5,246) 119.31,242.15 121.675,242.15
no net on Top Overlay "TOPOVERLAY405" (solid, pour order 0): 134.825,242.15 137.19,242.15 cw(c134,246) 134.825,241.069
no net on Top Overlay "TOPOVERLAY406" (solid, pour order 0): 133.175,241.069 cw(c134,246) 130.81,242.15 133.175,242.15
no net on Top Overlay "TOPOVERLAY407" (solid, pour order 0): 146.325,242.15 148.69,242.15 cw(c145.5,246) 146.325,241.069
no net on Top Overlay "TOPOVERLAY408" (solid, pour order 0): 144.675,241.069 cw(c145.5,246) 142.31,242.15 144.675,242.15
no net on Top Overlay "TOPOVERLAY409" (solid, pour order 0): 157.825,242.15 160.19,242.15 cw(c157,246) 157.825,241.069
no net on Top Overlay "TOPOVERLAY410" (solid, pour order 0): 156.175,241.069 cw(c157,246) 153.81,242.15 156.175,242.15
no net on Top Overlay "TOPOVERLAY411" (solid, pour order 0): 148.06,233.85 cw(c151.25,230) 150.425,234.931 150.425,233.85
no net on Top Overlay "TOPOVERLAY412" (solid, pour order 0): 152.075,233.85 152.075,234.931 cw(c151.25,230) 154.44,233.85
no net on Top Overlay "TOPOVERLAY413" (solid, pour order 0): 113.56,233.85 cw(c116.75,230) 115.925,234.931 115.925,233.85
no net on Top Overlay "TOPOVERLAY414" (solid, pour order 0): 117.575,233.85 117.575,234.931 cw(c116.75,230) 119.94,233.85
no net on Top Overlay "TOPOVERLAY415" (solid, pour order 0): 102.06,233.85 cw(c105.25,230) 104.425,234.931 104.425,233.85
no net on Top Overlay "TOPOVERLAY416" (solid, pour order 0): 106.075,233.85 106.075,234.931 cw(c105.25,230) 108.44,233.85
no net on Top Overlay "TOPOVERLAY417" (solid, pour order 0): 154.75,200.675 ccw(c155,200.675) 155.25,200.675 ccw(c155,200.675)
no net on Top Overlay "TOPOVERLAY418" (solid, pour order 0): 48.3,210.7 48.3,211.75 48.75,211.75 48.75,214.25 48.3,214.25 48.3,215.3 48.9,215.3 48.9,210.7
no net on Top Overlay "TOPOVERLAY419" (solid, pour order 0): 136.56,233.85 cw(c139.75,230) 138.925,234.931 138.925,233.85
no net on Top Overlay "TOPOVERLAY420" (solid, pour order 0): 140.575,233.85 140.575,234.931 cw(c139.75,230) 142.94,233.85
no net on Top Overlay "TOPOVERLAY421" (solid, pour order 0): 125.06,233.85 cw(c128.25,230) 127.425,234.931 127.425,233.85
no net on Top Overlay "TOPOVERLAY422" (solid, pour order 0): 129.075,233.85 129.075,234.931 cw(c128.25,230) 131.44,233.85
no net on Top Overlay "TOPOVERLAY423" (solid, pour order 0): 176.2,248.8 176.2,252.2 177.15,252.2 177.15,251.7 176.5,251.7 176.5,249.3 177.15,249.3 177.15,248.8
no net on Top Overlay "TOPOVERLAY424" (solid, pour order 0): 175.45,220.8 175.45,224.2 176.4,224.2 176.4,223.7 175.75,223.7 175.75,221.3 176.4,221.3 176.4,220.8
no net on Top Overlay "TOPOVERLAY425" (solid, pour order 0): 183.95,248.8 183.95,252.2 184.9,252.2 184.9,251.7 184.25,251.7 184.25,249.3 184.9,249.3 184.9,248.8
no net on Top Overlay "TOPOVERLAY426" (solid, pour order 0): 182.45,220.8 182.45,224.2 183.4,224.2 183.4,223.7 182.75,223.7 182.75,221.3 183.4,221.3 183.4,220.8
